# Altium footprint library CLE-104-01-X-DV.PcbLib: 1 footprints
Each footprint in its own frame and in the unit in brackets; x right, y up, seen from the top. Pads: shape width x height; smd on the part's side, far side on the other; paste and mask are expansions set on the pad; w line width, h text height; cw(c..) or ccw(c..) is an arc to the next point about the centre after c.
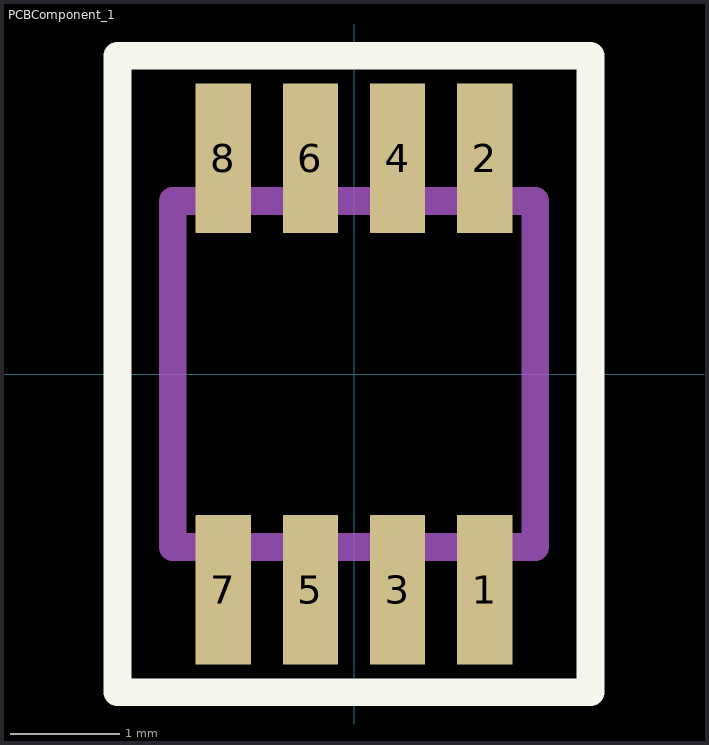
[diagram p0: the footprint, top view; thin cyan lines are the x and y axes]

## PCBComponent_1 [mil]
pads (8):
  rect 20x54 smd mask+2: 1(47.25,-78) 2(47.25,78) 3(15.75,-78) 4(15.75,78) 5(-15.75,-78) 6(-15.75,78) 7(-47.25,-78) 8(-47.25,78)
Top Overlay:
  lines w10: -85.5,-115 85.5,-115 85.5,115 -85.5,115 -85.5,-115
Mechanical 1:
  lines w10: -65.5,-62.5 65.5,-62.5 65.5,62.5 -65.5,62.5 -65.5,-62.5
  text "J1" at -14.64,-15 h25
